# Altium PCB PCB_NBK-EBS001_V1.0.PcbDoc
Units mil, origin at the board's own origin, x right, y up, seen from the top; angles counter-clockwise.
Board outline 2763 x 2782 mil, 2 copper layers (Top Layer, Bottom Layer); 39 components, 56 nets, 181 pads, 30 vias.
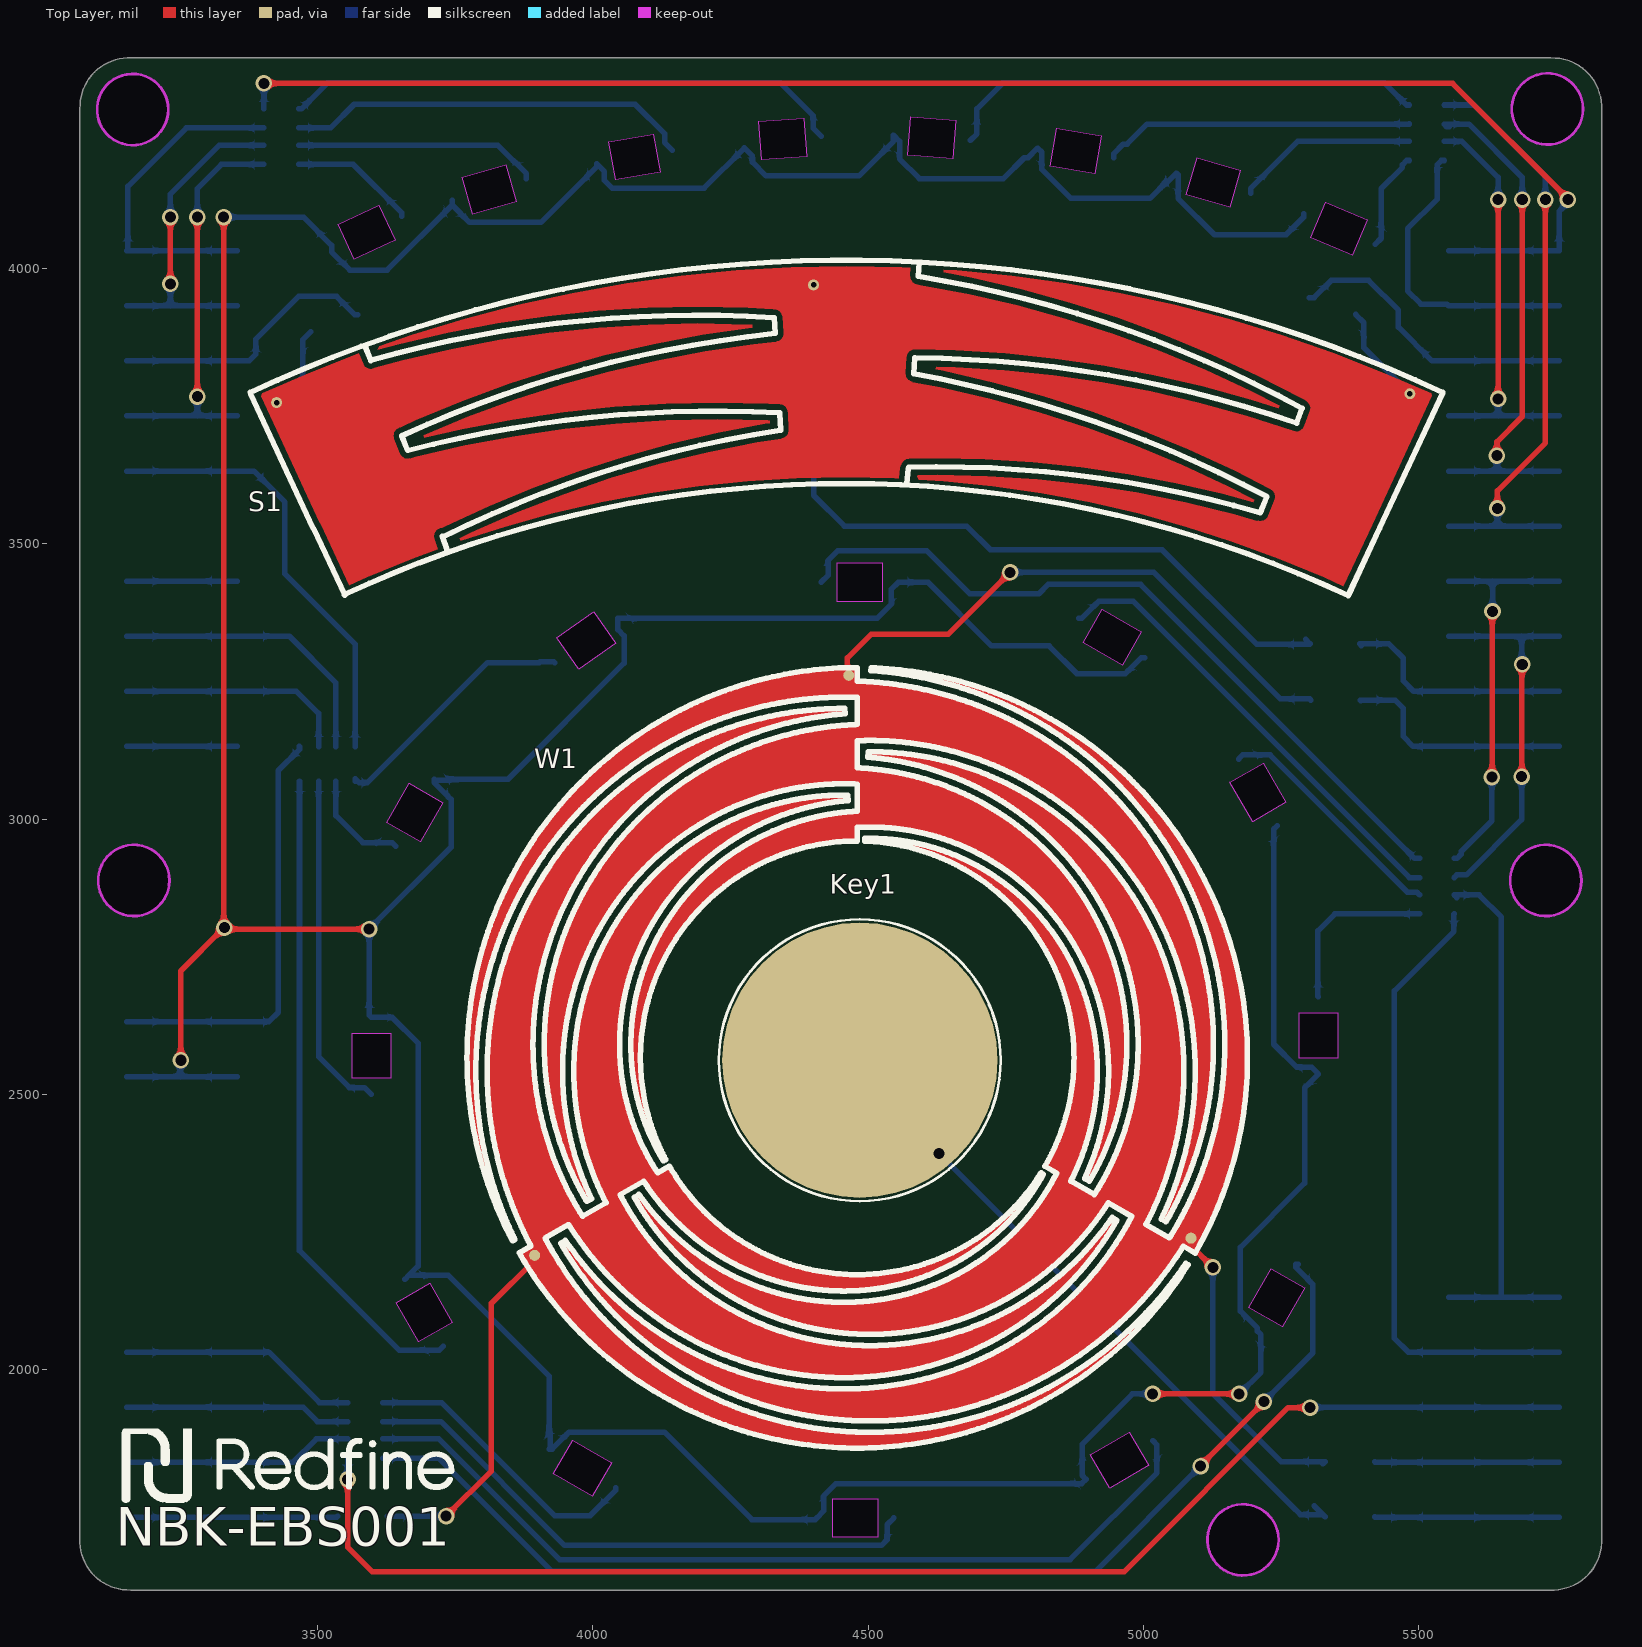
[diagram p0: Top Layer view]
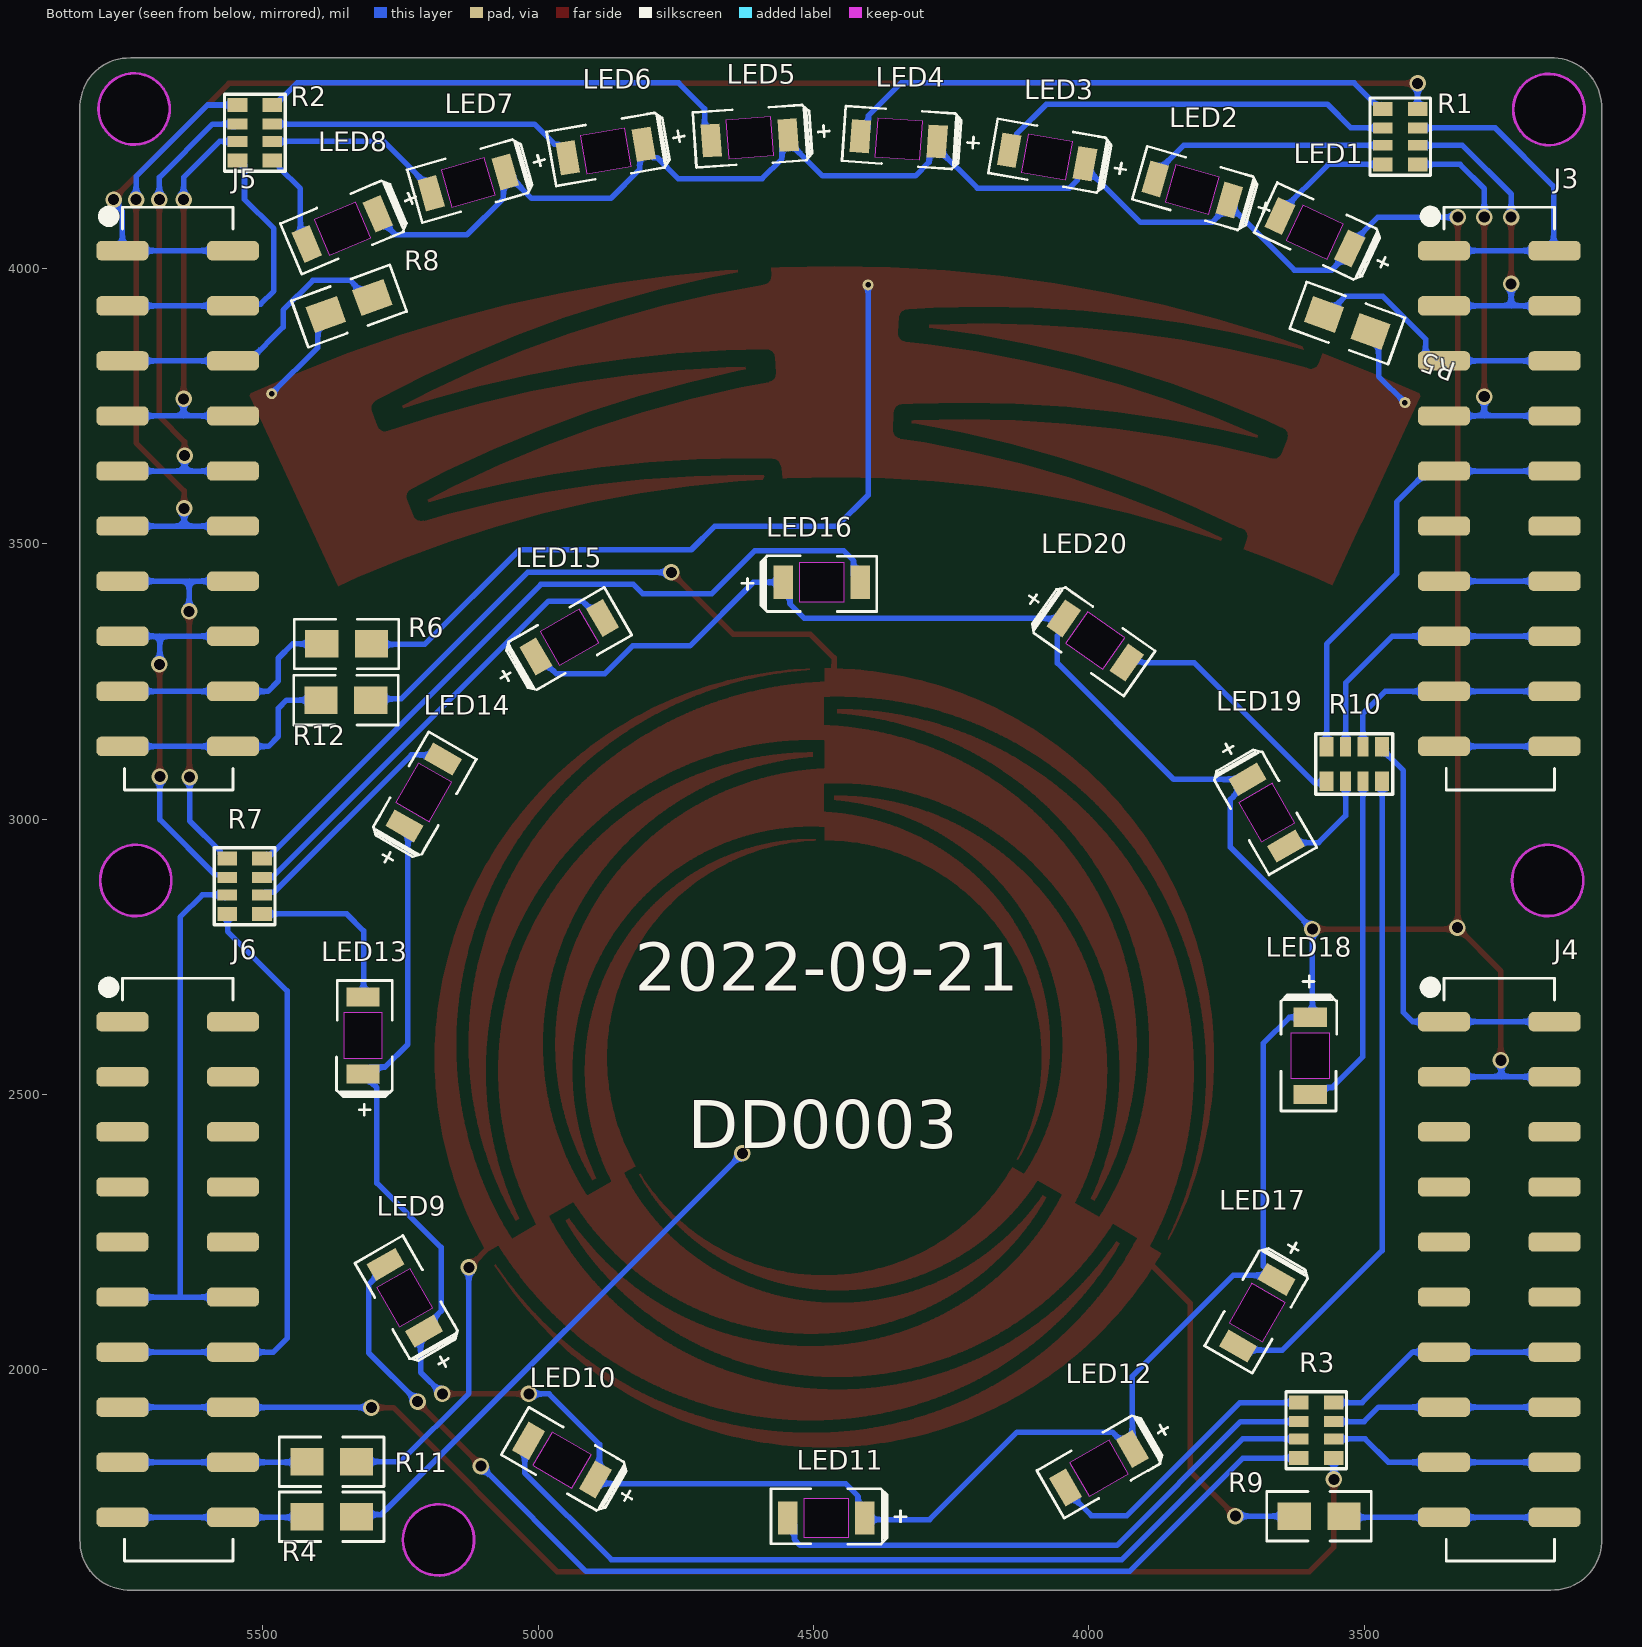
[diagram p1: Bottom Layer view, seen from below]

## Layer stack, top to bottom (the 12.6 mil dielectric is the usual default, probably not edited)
Top Solder: solder mask 0.4, Solder Resist, Dk 3.5
Top Layer: signal copper 1.4
Dielectric 1: dielectric 12.6, FR-4, Dk 4.8
Bottom Layer: signal copper 1.4
Bottom Solder: solder mask 0.4, Solder Resist, Dk 3.5

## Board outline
3069,1686 3069,4290 cw(c3158,4293) 3155,4382 5740,4382 cw(c5743,4293) 5832,4296 5832,1692 cw(c5743,1689) 5746,1600 3161,1600 cw(c3158,1689)
cut-out: 5116.28,1691 ccw(c5181,1691) 5181,1626.29 ccw(c5181,1691) 5245.72,1691 ccw(c5181,1691) 5181,1755.71 ccw(c5181,1691)
cut-out: 5665.98,2888.43 ccw(c5730.69,2888.43) 5730.69,2823.71 ccw(c5730.69,2888.43) 5795.41,2888.43 ccw(c5730.69,2888.43) 5730.69,2953.14 ccw(c5730.69,2888.43)
cut-out: 3101.98,2888.43 ccw(c3166.69,2888.43) 3166.69,2823.71 ccw(c3166.69,2888.43) 3231.41,2888.43 ccw(c3166.69,2888.43) 3166.69,2953.14 ccw(c3166.69,2888.43)
cut-out: 5668.98,4289.43 ccw(c5733.69,4289.43) 5733.69,4224.71 ccw(c5733.69,4289.43) 5798.41,4289.43 ccw(c5733.69,4289.43) 5733.69,4354.14 ccw(c5733.69,4289.43)
cut-out: 3164.69,4223.71 cw(c3164.69,4288.43) 3099.98,4288.43 cw(c3164.69,4288.43) 3164.69,4353.14 cw(c3164.69,4288.43) 3229.41,4288.43 cw(c3164.69,4288.43)

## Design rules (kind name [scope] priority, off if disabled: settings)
Clearance [All] p1: gap=7 ignorepadtopadclearanceinfootprint=FALSE
MinimumSolderMaskSliver [All] p1: minsoldermaskwidth=0
PolygonConnect [All] p1: connectstyle=Relief reliefconductorwidth=10 reliefentries=4 polygonreliefangle="90 Angle" airgapwidth=10
RoutingVias [All] p1: holewidth=20 width=30 viastyle="Through Hole" minholewidth=10 minwidth=10 maxholewidth=28 maxwidth=50
SilkToSilkClearance [All] p1: silktosilkclearance=0
SilkToSolderMaskClearance [IsPad] p1: minsilkscreentomaskgap=0 clearancetoexposedcopper=TRUE
SolderMaskExpansion [All] p1: expansion=4 istentingtop=FALSE
Width [All] p1: maxlimit=10 minlimit=10 preferedwidth=10
27 further rules are at their usual default settings.

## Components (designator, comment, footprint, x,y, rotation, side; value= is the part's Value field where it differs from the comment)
J3 "CON2*10" TP-2.54-10P 3355,4032 r270 bottom locked
J4 "CON2*10" TP-2.54-10P 3355,2632 r270 bottom locked
J5 "CON2*10" TP-2.54-10P 5755,4032 r270 bottom locked
J6 "CON2*10" TP-2.54-10P 5755,2632 r270 bottom locked
Key1 "DH" "TK PAD-3" 4485,2562 r0 top
LED1 "LS-SP170UHR24" LED1206 3467.84,4113.48 r25 bottom
LED2 "LS-SP170UHR24" LED1206 3699.59,4209.81 r16 bottom
LED3 "LS-SP170UHR24" LED1206 3970.81,4280.08 r10 bottom
LED4 "LS-SP170UHR24" LED1206 4248.76,4323.61 r4 bottom
LED5 "LS-SP170UHR24" LED1206 4532.68,4338.16 r356 bottom
LED6 "LS-SP170UHR24" LED1206 4804.93,4322.34 r350 bottom
LED7 "LS-SP170UHR24" LED1206 5066.96,4271.83 r344 bottom
LED8 "LS-SP170UHR24" LED1206 5309.71,4194.26 r337 bottom
LED9 "LS-SP170UHR24" LED1206 5114.73,2100.18 r60 bottom
LED10 "LS-SP170UHR24" LED1206 4831.18,1873.27 r30 bottom
LED11 "LS-SP170UHR24" LED1206 4387,1826 r0 bottom
LED12 "LS-SP170UHR24" LED1206 3950.94,1948.27 r330 bottom
LED13 "LS-SP170UHR24" LED1206 5223,2517 r90 bottom
LED14 "LS-SP170UHR24" LED1206 5170.73,2922.94 r120 bottom
LED15 "LS-SP170UHR24" LED1206 4973.82,3202.73 r150 bottom
LED16 "LS-SP170UHR24" LED1206 4575,3335 r180 bottom
LED17 "LS-SP170UHR24" LED1206 3731.27,2229.06 r300 bottom
LED18 "LS-SP170UHR24" LED1206 3693,2660 r270 bottom
LED19 "LS-SP170UHR24" LED1206 3804.27,3042.06 r240 bottom
LED20 "LS-SP170UHR24" LED1206 4116.55,3297.95 r215 bottom
R1 "510R" RCA-8P4R-0603 3434.5,4239.25 r270 bottom
R2 "510R" RCA-8P4R-0603 5514.5,4246.25 r90 bottom
R3 "510R" RCA-8P4R-0603 3587,1890 r270 bottom
R4 "2.2K" R0805 5330,1733 r0 bottom
R5 "2.2K" R0805 3488.43,3885.22 r20 bottom
R6 "2.2K" R0805 5303,3318 r0 bottom
R7 "510R" RCA-8P4R-0603 5533,2878 r90 bottom
R8 "2.2K" R0805 5385.57,3916.22 r160 bottom
R9 "2.2K" R0805 3627,1734 r180 bottom
R10 "510R" RCA-8P4R-0603 3518,3100 r180 bottom
R11 "2.2K" R0805 5330,1833 r0 bottom
R12 "2.2K" R0805 5304,3216 r0 bottom
S1 "SlideBar3" "PCBCOMPONENT_1 - duplicate" 3426,3756.22 r0 top locked
W1 "Wheel3" 滑轮10-18-3 51385.53,51577 r0 top locked

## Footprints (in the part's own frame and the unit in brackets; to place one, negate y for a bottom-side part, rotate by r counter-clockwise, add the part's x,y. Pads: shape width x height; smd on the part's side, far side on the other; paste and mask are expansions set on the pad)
LED1206 [mil]
  rect 35x60 smd: 1(20,95) 2(160,95)
  Keep-Out Layer board cut-out: 49,60 131,60 131,130 49,130
  silkscreen extent -55,42 190,143
"PCBCOMPONENT_1 - duplicate" [mil]
  round 20 hole 10 mask+4: 1(0,0) 2(975,213.78) 3(2058,16.12)
  Top Layer region: 220 vertices and 0 holes, not listed, extent 183.45,-251.14 1821.21,247.99
  Top Layer region: 1235.23,240.12 1334.95,230.3 1434.22,216.57 1532.87,198.95 1630.75,177.47 1727.71,152.17 1823.61,123.08 1918.29,90.25 2011.6,53.73 2096.32,16.67 2098.09,11.99 1989.19,-221.56 1989.17,-221.58 1937.02,-333.42 1902.51,-317.43 1819.85,-283.19 1735.85,-252.39 1650.64,-225.1 1564.38,-201.34 1477.21,-181.18 1389.28,-164.63 1300.75,-151.73 1211.75,-142.5 1166.21,-139.67 1163,-135.02 1164.1,-132.21 1199.29,-131.44 1290.22,-133.43 1380.97,-139.38 1471.38,-149.28 1561.27,-163.11 1650.48,-180.86 1738.82,-202.48 1781.98,-215.06 1782.1,-214.64 1783.38,-214.88 1786.31,-215.47 1786.38,-215.45 1786.44,-215.47 1789.14,-214.9 1792.16,-214.3 1792.22,-214.26 1792.28,-214.25 1794.51,-212.73 1797.13,-210.99 1797.17,-210.93 1797.22,-210.89 1798.68,-208.66 1800.44,-206.03 1800.46,-205.95 1800.49,-205.9 1811.75,-178.03 1811.82,-177.67 1812.47,-176.7 1813.63,-170.85 1812.47,-165 1809.15,-160.04 1805.39,-157.53 1805.43,-157.46 1740.61,-124.1 1655.86,-84.81 1569.55,-49.06 1481.84,-16.91 1392.87,11.59 1302.81,36.39 1211.79,57.45 1197.26,60.18 1197.78,65.17 1232.04,64.46 1321.46,58.91 1410.58,49.67 1499.24,36.75 1587.29,20.18 1674.57,-0.01 1760.95,-23.8 1845.87,-51 1846.81,-51.58 1849.75,-52.06 1852.1,-52.53 1852.34,-52.48 1852.7,-52.54 1856.23,-51.7 1857.95,-51.36 1858.1,-51.26 1858.51,-51.16 1861.86,-48.75 1862.91,-48.05 1862.98,-47.94 1863.35,-47.67 1865.68,-43.91 1866.23,-43.08 1866.25,-42.98 1866.49,-42.6 1876.56,-15.57 1877,-12.9 1877.53,-10.22 1877.48,-9.95 1877.52,-9.68 1876.9,-7.07 1876.37,-4.37 1876.21,-4.14 1876.15,-3.87 1874.59,-1.72 1873.05,0.59 1872.81,0.75 1872.66,0.97 1870.41,2.36 1869.45,3 1869.58,3.23 1863.07,6.93 1781.7,48.82 1698.66,87.31 1614.11,122.33 1528.18,153.83 1441.02,181.75 1352.79,206.05 1263.62,226.67 1211.29,236.52 1211.9,241.49
  Top Layer region: 855.24,141.78 863.52,141.27 863.62,136.25 863.11,136.2 773.21,123.1 683.92,106.3 595.4,85.82 507.81,61.7 421.28,33.98 335.98,2.71 252.04,-32.06 225.46,-44.38 221.97,-45.85 221.49,-45.95 221.01,-46.26 220.9,-46.31 218.95,-47.62 216.5,-49.22 216.46,-49.27 216.41,-49.31 214.79,-51.74 213.14,-54.15 213.13,-54.22 213.09,-54.27 212.52,-57.14 211.93,-59.99 211.94,-60.06 211.93,-60.13 212.5,-62.98 213.04,-65.86 223.85,-92.61 223.89,-92.67 223.9,-92.74 225.52,-95.16 227.12,-97.61 227.18,-97.64 227.22,-97.7 229.65,-99.32 232.06,-100.96 232.12,-100.98 232.18,-101.02 235.05,-101.59 237.9,-102.18 237.97,-102.17 238.03,-102.18 240.89,-101.61 241.8,-101.44 241.84,-101.63 252.67,-98.65 342.46,-77.88 433.02,-60.83 524.22,-47.54 615.88,-38.04 707.86,-32.33 800,-30.42 892.14,-32.33 895.33,-32.53 895.53,-37.55 886.88,-38.81 800.96,-54.98 715.79,-74.68 631.5,-97.89 548.25,-124.56 466.17,-154.65 385.4,-188.11 306.08,-224.87 301.25,-227.36 295.94,-228.08 290.78,-231.09 287.17,-235.84 285.66,-241.61 286.46,-247.53 292.85,-266.07 246.15,-283.19 163.49,-317.43 132.27,-331.9 80.83,-221.59 78.51,-218.43 -28.12,11.98 -26.35,16.66 58.4,53.73 149.33,89.32 156.95,70.44 160.23,65.45 165.16,62.09 171,60.87 176.86,61.99 178.18,62.85 228.95,76.83 316.88,97.17 405.58,113.87 494.9,126.88 584.68,136.19 674.76,141.78 765,143.65
  silkscreen extent -48,-350 2118,258
R0805 [mil]
  rect 60x50 smd: 1(0,0) 2(90,0)
  silkscreen extent -50,-45 140,45
RCA-8P4R-0603 [mm] "3.2mm*1.6mm*0.6mm(长*宽*厚)"
  rect 0.65x0.9 smd: 1(-1.28,-0.8) 4(1.28,-0.8) 5(1.28,0.8) 8(-1.28,0.8)
  rect 0.5x0.9 smd: 2(-0.4,-0.8) 3(0.4,-0.8) 6(0.4,0.8) 7(-0.4,0.8)
  silkscreen extent -1.78,-1.4 1.78,1.4, body extent -1.6,-0.8 1.6,0.8, height 0.6
"TK PAD-3" [mil] "隔空按键"
  round 500 smd mask+4: 1(0,0)
  silkscreen extent -256,-256 256,256
TP-2.54-10P [mm] "2.54mm间距贴片排母SMT"
  rrect50% 0.89x2.4 smd: 1(0,0) 2(0,5.1) 3(2.54,0) 4(2.54,5.1) 5(5.08,0) 6(5.08,5.1) 7(7.62,0) 8(7.62,5.1) 9(10.16,0) 10(10.16,5.1) 11(12.7,0) 12(12.7,5.1) 13(15.24,0) 14(15.24,5.1) 15(17.78,0) 16(17.78,5.1) 17(20.32,0) 18(20.32,5.1) 19(22.86,0) 20(22.86,5.1)
  silkscreen extent -2,-0.87 24.88,5.1
滑轮10-18-3 [mil]
  round 20 smd paste+0: 1(-46920.53,-48316) 2(-46299.03,-49338.11) 3(-47490.91,-49369.25)
  Top Layer region: 7206 vertices and 0 holes, not listed, extent -47612.57,-49341.21 -46259.5,-48303.2
  Top Layer region: 7199 vertices and 0 holes, not listed, extent -47575.87,-49717.96 -46306.17,-48377.41
  Top Layer region: 7194 vertices and 0 holes, not listed, extent -47441.67,-49668.76 -46197.79,-48303.7
  silkscreen extent -47614,-49719 -46197,-48302

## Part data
LED1 LED2 LED3 LED4 LED5 LED6 LED7 LED8 LED9 LED10 LED11 LED12 LED13 LED14 LED15 LED16 LED17 LED18 LED19 LED20: library part LED-LS-SP170UHR24, "绿色；贴片"
R1 R2 R3 R7 R10: library part R-8P4R, "贴片排阻"
R4 R5 R6 R8 R9 R11 R12: library part R0805

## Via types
v1: diameter 30, hole 20, Top Layer to Bottom Layer, tented both sides, 30 vias

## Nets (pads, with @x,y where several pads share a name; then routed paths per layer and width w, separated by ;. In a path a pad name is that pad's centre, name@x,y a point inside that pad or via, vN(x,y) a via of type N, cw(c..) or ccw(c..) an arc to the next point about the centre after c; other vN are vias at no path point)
0: J5.3 J5.4 R2.8 | length 553.3
  Bottom Layer w10: R2.8 5541.07,4195.86 5533.28,4188.06 5533.28,4125.31 5480,4072.03 5480,3959 5503.97,3935.03 5551.18,3935.03 J5.4 J5.3
1: J5.1 J5.2 R1.8 | length 2801.9
  Top Layer w10: v1(3403,4336) 5561.43,4336 v1@5771,4126.43
  Bottom Layer w10: R1.8@3402.75,4289.39 R1.8 v1(3403,4336) ; J5.2 J5.1 5755,4103.59 5771,4119.59 v1(5771,4125)
2: J3.1 J3.2 R1.7 | length 609.4
  Bottom Layer w10: J3.1 J3.2 3156,4033.79 3156,4149 3262,4255 R1.7
3: J3.3 J3.4 R1.6 | length 613.3
  Top Layer w10: v1(3233,3972) v1(3233,4093)
  Bottom Layer w10: J3.4 3233,3932 ; v1@3231,4091 v1(3233,4093) 3233,4135 3321.5,4223.5 R1.6 ; v1(3233,3972) 3233,3932 ; J3.3 3233,3932
5: J3.7 J3.8 R1.5 | length 753
  Top Layer w10: v1(3282,3767) v1(3282,4093)
  Bottom Layer w10: J3.8 3282,3732 ; v1(3282,3767) 3282,3732 ; v1(3282,4093) 3282,4145 3325.86,4188.86 R1.5 ; J3.7 3282,3732
24: J5.11 J5.12 R2.5 | length 1109.5
  Top Layer w10: v1(5643,3564) 5643,3596 5730,3683 v1(5730,4125)
  Bottom Layer w10: R2.5 5600.35,4296.65 5730,4167 v1(5730,4125) ; J5.12 5643,3532 ; v1(5643,3564) 5643,3532 ; J5.11 5643,3532
25: J5.9 J5.10 R2.6 | length 946.9
  Top Layer w10: v1(5642,3660) 5642,3685 5688,3731 v1(5688,4125)
  Bottom Layer w10: J5.10 5642,3632 ; R2.6@5555.84,4257.16 5550.83,4257.16 R2.6 5591,4262 5688,4165 v1(5688,4125) ; v1(5642,3660) 5642,3632 ; J5.9 5642,3632
26: J5.7 J5.8 R2.7 | length 758.9
  Top Layer w10: v1(5644,3763) v1(5644,4125)
  Bottom Layer w10: R2.7 5578.5,4230.5 5644,4165 v1(5644,4125) ; J5.8 5644,3732 ; v1(5644,3763) 5644,3732 ; J5.7 5644,3732
GND: J3.13 J3.14 | length 200.8
  Bottom Layer w10: J3.14 J3.13
NetKey1_1: Key1.1 R4.1 | length 998
  Bottom Layer w10: v1@4629,2394 v1(4629,2393) 5269,1753 5285,1737 R4.1@5326,1737 ; R4.1@5310,1753 R4.1@5326,1737 ; R4.1 R4.1@5326,1737
NetLED1_2: LED1.2 R1.4 | length 229.4
  Bottom Layer w10: R1.4 3565.19,4188.86 3653,4101.05 LED1.2
NetLED2_2: LED2.2 R1.3 | length 444.3
  Bottom Layer w10: R1.3 3828,4223.5 3879.58,4171.93 LED2.2
NetLED3_2: LED3.2 R1.2 | length 740.7
  Bottom Layer w10: R1.2 3524,4255 3567,4298 4077.19,4298 4130.58,4244.61 4130.58,4228.61 LED3.2
NetLED4_2: LED4.2 R1.1 | length 1022.1
  Bottom Layer w10: R1.1 3470.91,4289.65 3518.27,4337 4340.73,4337 4400.45,4277.28 4400.45,4254.55 LED4.2
NetLED5_2: LED5.2 R2.4 | length 884.1
  Bottom Layer w10: LED5.2 4697.77,4244.34 4697.77,4289.77 4745,4337 5437.72,4337 5478.08,4296.65 R2.4
NetLED6_2: LED6.2 R2.3 | length 567
  Bottom Layer w10: LED6.2 4946,4207.99 4963.44,4225.43 4970.43,4225.43 5007,4262 R2.3 R2.3@5482.54,4262.46
NetLED7_2: LED7.2 R2.2 | length 332.4
  Bottom Layer w10: LED7.2 5194.58,4144.98 5280.1,4230.5 R2.2
NetLED8_2: LED8.2 R2.1 | length 181.1
  Bottom Layer w10: LED8.2@5420.73,4043.43 5431.95,4054.65 5431.95,4144.81 5470.28,4183.14 5470.28,4188.06 5478.08,4195.86 R2.1
NetLED9_2: LED9.2 R3.4 | length 2117.8
  Top Layer w10: v1(5104,1825) 5104,1826 5219,1941 v1(5219,1942)
  Bottom Layer w10: R3.4 3720.39,1839.61 3926,1634 4913,1634 v1(5104,1825) ; v1(5219,1942) 5307.81,2030.81 5307.81,2154.84 5277,2185.65 LED9.2 LED9.2@5281.58,2191.24
NetLED10_2: LED10.2 R3.3 | length 1623.7
  Bottom Layer w10: R3.3 3720.75,1874.25 3940,1655 4867,1655 5024.63,1812.63 5024.63,1863.62 LED10.2
NetLED11_2: LED11.2 R3.2 | length 1058.2
  Bottom Layer w10: R3.2 3724.25,1905.75 3949,1681 4524.21,1681 4534.5,1691.29 4534.5,1718.5 LED11.2
NetLED12_2: LED12.2 R3.1 | length 532.4
  Bottom Layer w10: R3.1 3725.61,1940.39 3931,1735 3995.58,1735 4042,1781.42 LED12.2
NetLED13_2: LED13.2 R7.1 | length 317.6
  Bottom Layer w10: LED13.2 5317,2678 5317,2797 5347.61,2827.61 R7.1
NetLED14_2: LED14.2 R7.2 | length 436.8
  Bottom Layer w10: LED14.2 5180.38,3116.38 5230.1,3116.38 5479.39,2867.09 5496.66,2867.09 R7.2
NetLED15_2: LED15.2 R7.3 | length 839.5
  Bottom Layer w10: LED15.2 4888.35,3365 4919.16,3395.81 4981.19,3395.81 5483.25,2893.75 R7.3
NetLED16_2: LED16.2 R7.4 | length 1371.5
  Bottom Layer w10: LED16.2 4427.5,3442.5 4427.5,3469.71 4444.79,3487 4607,3487 4685,3409 4810,3409 4827,3426 4995,3426 5492.61,2928.39 R7.4
NetLED17_2: LED17.2 R10.4 | length 1191.4
  Bottom Layer w10: R10.4 3467.61,2216.39 3648.38,2035.62 3721.62,2035.62 LED17.2
NetLED18_2: LED18.2 R10.3 | length 624.1
  Bottom Layer w10: R10.3 3502.25,2568.54 3558.29,2512.5 3585.5,2512.5 LED18.2
NetLED19_2: LED19.2 R10.2 | length 193.4
  Bottom Layer w10: R10.2 3533.75,3006.25 3582.75,2957.25 3635.75,2957.25 LED19.2
NetLED20_2: LED20.2 R10.1 | length 462.5
  Bottom Layer w10: R10.1 3568.39,3073.43 3575.82,3066 3591,3066 3809,3284 3902.58,3284 3904.46,3285.87 3929.13,3285.87 LED20.2
NetR5_1: R5.1 S1.1 | length 154.9
  Bottom Layer w10: S1.1 3473.79,3804.01 3473.79,3870.58 R5.1
NetR6_1: R6.1 S1.2 | length 1408.7
  Bottom Layer w10: S1.2 4401,3588 4457,3532 4679,3532 4722,3489 5034,3489 5206,3317 5302,3317 R6.1 R6.1@5294.46,3326.54
NetR8_1: R8.1 S1.3 | length 184.7
  Bottom Layer w10: R8.1 5400.21,3901.58 5400.21,3856.12 S1.3
NetR9_1: R9.1 W1.3 | length 635.4
  Top Layer w10: v1(3734,1734) 3816,1816 3816,2120.74 3892.12,2196.86
  Bottom Layer w10: R9.1 v1(3734,1734)
NetR11_1: R11.1 W1.2 | length 549.4
  Top Layer w10: 5084,2228 v1(5126,2186)
  Bottom Layer w10: v1(5126,2186) 5126,1957 5250,1833 R11.1 R11.1@5326,1829
NetR12_1: R12.1 W1.1 | length 1044.4
  Top Layer w10: 4462.5,3250.11 4462.5,3292.5 4506,3336 4646,3336 v1(4758,3448)
  Bottom Layer w10: v1(4758,3448) 5019,3448 5249,3218 5302,3218 R12.1
P06: J3.9 J3.10 R10.8 | length 807.1
  Bottom Layer w10: J3.10 J3.9 3384.72,3632 3441,3575.72 3441,3445 3568.39,3317.61 R10.8
P22: J5.15 J5.16 R7.6 | length 700.6
  Top Layer w10: v1(5687,3077) 5687.5,3077.5 5687.5,3280.5 v1(5688,3281)
  Bottom Layer w10: J5.16 5687,3332 ; R7.6 5569.34,2898.59 5586.42,2898.59 5687,2999.17 v1(5687,3077) ; v1(5688,3281) 5687,3282 5687,3332 ; J5.15 5687,3332
P23: J5.13 J5.14 R7.5 | length 736.1
  Top Layer w10: v1(5633,3076) 5633.5,3076.5 5633.5,3376.5 v1(5634,3377)
  Bottom Layer w10: J5.14 5634,3432 ; R7.5 5569.42,2928.39 5577.21,2936.19 5577.21,2941.11 5633,2996.9 v1(5633,3076) ; v1(5634,3377) 5634,3432 ; J5.13 5634,3432
P31: J6.11 J6.12 R7.7 | length 1000.2
  Bottom Layer w10: J6.12 5651,2132 ; R7.7@5569.34,2857.41 R7.7 5609.75,2862.25 5650,2822 5650,2793.83 5650,2133 5651,2132 ; J6.11 5651,2132
P32: J6.13 J6.14 R7.8 | length 1124.9
  Bottom Layer w10: R7.8 5564,2827.11 5564,2796 5456,2688 5456,2057 5481,2032 J6.14 J6.13
P33: J6.15 J6.16 R3.5 | length 2504.3
  Top Layer w10: v1(3555,1801) 3555,1678 3600,1633 4965,1633 5263,1931 v1(5303,1931)
  Bottom Layer w10: v1(3555,1801) 3555,1839.1 R3.5 ; v1(5303,1931) 5303.5,1931.5 5553.71,1931.5 J6.16 J6.15
P37: J4.17 J4.18 R3.6 | length 418.8
  Bottom Layer w10: J4.18 J4.17 3456,1832 3498.25,1874.25 R3.6
P40: J4.15 J4.16 R3.7 | length 412.2
  Bottom Layer w10: J4.16 J4.15 3474,1932 3500.25,1905.75 R3.7
P41: J4.13 J4.14 R3.8 | length 439.2
  Bottom Layer w10: J4.14 J4.13 3412,2032 3503.61,1940.39 R3.8
P46: J4.1 J4.2 R10.5 | length 781
  Bottom Layer w10: J4.2 J4.1 3412,2632 3429.02,2649.02 3429.02,3087.98 3467.61,3126.57 R10.5 R10.5@3467.1,3132
P50: J3.15 J3.16 R10.7 | length 530.4
  Bottom Layer w10: J3.16 J3.15 3449,3332 3533.75,3247.25 R10.7
P51: J3.17 J3.18 R10.6 | length 425
  Bottom Layer w10: J3.18 J3.17 3462,3232 3502.25,3191.75 R10.6
TK1: J4.19 J4.20 R9.2 | length 383.6
  Bottom Layer w10: J4.20 J4.19 3535,1732 R9.2
TK2: J6.19 J6.20 R4.2 | length 335.4
  Bottom Layer w10: R4.2 5421,1732 J6.20 J6.19
TK3: J6.17 J6.18 R11.2 | length 335.4
  Bottom Layer w10: R11.2 5421,1832 J6.18 J6.17
TK16: J5.19 J5.20 R12.2 | length 427.1
  Bottom Layer w10: R12.2@5395,3215 R12.2 5457,3216 5472,3201 5472,3150 5490,3132 J5.20 J5.19
TK17: J5.17 J5.18 R6.2 | length 425.9
  Bottom Layer w10: R6.2@5396,3315 R6.2 5446,3318 5472,3292 5472,3251 5491,3232 J5.18 J5.17
TK23: J5.5 J5.6 R8.2 | length 545.2
  Bottom Layer w10: R8.2 5310.19,3947 5341.19,3978 5409,3978 5463,3924 5463,3893.49 5524.49,3832 J5.6 J5.5
TK28: J3.5 J3.6 R5.2 | length 496.9
  Bottom Layer w10: J3.6 J3.5 3376.25,3832 3388.48,3844.23 3388.48,3871.48 3466,3949 3534.81,3949 3567.81,3916 R5.2
VDD: J4.3 J4.4 LED1.1 LED2.1 LED3.1 LED4.1 LED5.1 LED6.1 LED7.1 LED8.1 LED9.1 LED10.1 LED11.1 LED12.1 LED13.1 LED14.1 LED15.1 LED16.1 LED17.1 LED18.1 LED19.1 LED20.1 | length 10331.7
  Top Layer w10: v1(3252,2562) 3252,2724 v1@3330,2802 ; v1(3330,4093) v1@3330,2802 ; v1(3331,2803) v1@3330,2802 ; v1(3594,2800) 3330,2800 v1@3330,2802 ; v1(5017,1956) v1(5174,1956)
  Bottom Layer w10: J4.4 3251,2532 ; v1(3252,2562) 3251,2561 3251,2532 ; v1(3330,4093) 3475,4093 3526.12,4041.88 LED1.1 3526.12,4029.79 3558.9,3997 3626.57,3997 LED2.1@3745,4115.43 ; J4.3 3251,2532 ; LED17.1 LED17.1@3666.38,2171.63 ; LED2.1 LED2.1@3745,4115.43 ; 4879,3264.19 4828.69,3314.5 4724.5,3314.5 4609,3430 LED16.1 4542.5,3417.5 4542.5,3390.29 4516.51,3364.3 LED20.1 4045.68,3344.08 4057,3332.77 4057,3283 3846.24,3072.24 3743.65,3072.24 3741.73,3070.33 3713.92,3070.33 LED19.1 3712,3066.65 3742.81,3035.84 3742.81,2948.81 v1(3594,2800) 3594,2644 LED18.1 3636,2640 3683,2593 3683,2188.24 LED17.1@3666.38,2171.63 ; 4879.19,3264 4967.41,3264 4996.49,3293.08 LED15.1@5002.08,3293.08 ; v1(5017,1956) 4980,1956 4888.62,1864.62 4888.62,1808.38 LED10.1 4888,1793 4441.79,1793 4419.5,1770.71 4419.5,1743.5 LED11.1 4404,1728 4289,1728 4130.19,1886.81 3957.16,1886.81 3926.35,1856 LED12.1 3922.67,1857.92 3922.67,1885.73 3920.76,1887.65 3920.76,1988.24 3737.37,2171.63 LED17.1@3666.38,2171.63 ; v1(5174,1956) 5213.25,1995.25 5213.25,2063.75 LED9.1 5207,2075.59 5176.19,2106.4 5176.19,2222.19 5293,2339 5293,2512 LED13.1 5305.5,2549.5 5278.29,2549.5 5236.75,2591.04 5236.75,2981.51 LED14.1 ; LED8.1 5291,4092.82 5259.18,4061 5129.38,4061 5063.23,4127.15 5063.23,4169.92 5060,4173.15 5039.91,4153.06 5038.06,4153.06 5012,4127 4868.2,4127 4815.61,4179.59 4815.61,4210.84 4808.13,4218.32 4790.68,4200.88 4783.69,4200.88 4745.82,4163 4593.34,4163 4557.49,4198.85 4557.49,4230.51 LED5.1 4546,4230.4 4483.6,4168 4314.84,4168 4289.89,4192.95 4289.89,4204.09 4275.34,4218.64 4202.27,4145.57 4035.42,4145.57 4021.29,4159.7 4021.29,4175.71 LED3.1 4007,4184.28 3906.07,4083.35 3776.31,4083.35 3745,4114.66 LED2.1@3745,4115.43
pads on no net: J3.11 J3.12 J3.19 J3.20 J4.5 J4.6 J4.7 J4.8 J4.9 J4.10 J4.11 J4.12 J6.1 J6.2 J6.3 J6.4 J6.5 J6.6 J6.7 J6.8 J6.9 J6.10
copper on no net: | length 200.8
  Bottom Layer w10: 3154.21,3132 3355,3132

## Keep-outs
Keep-Out Layer:
  circle w5: c3166.69,2888.43 r64.72
  circle w5: c5733.69,4289.43 r64.72
  circle w5: c5181,1691 r64.72
  circle w5: c5730.69,2888.43 r64.72
  circle w5: c3164.69,4288.43 r64.72

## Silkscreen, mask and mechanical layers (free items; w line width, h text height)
Top Overlay:
  drawing of 10 lines, arcs and shapes, not listed
  text "NBK-EBS001" at 3134,1657 h120
Bottom Overlay:
  text "2022-09-21" at 4825,2659 h150
  text "DD0003" at 4728.33,2373 h150
Mechanical 1:
  circle w5: c3164,4288 r64.72
  circle w5: c5730,2888 r64.72
  circle w5: c5180.31,1690.57 r64.72
  circle w5: c5733,4289 r64.72
  circle w5: c3166,2888 r64.72
  lines w10: 3069,1686 ccw(c3158,1689) 3161,1600 5746,1600 ccw(c5743,1689) 5832,1692 5832,4296 ccw(c5743,4293) 5740,4382 3155,4382 ccw(c3158,4293) 3069,4290 3069,1686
